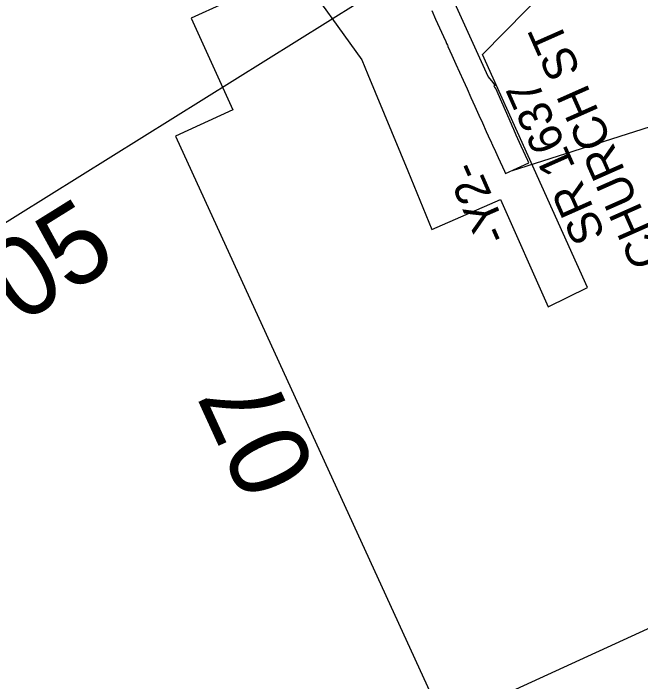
# Model space of a CAD drawing. Extents: x 2038094 to 2053858, y 751760 to 764312.
# Drawn here: x 2047889 to 2048875, y 757655 to 758704 of the extents above; entities that cross this region are included whole.
import ezdxf

# ---------------------------------------------------------------- set-up
doc = ezdxf.new("R2010")
doc.units = 0
for name, color, linetype in [('Old_Level_14', 7, 'Continuous'), ('Old_Level_2', 7, 'Continuous'), ('Prop Shade Light', 7, 'Continuous'), ('Scratch_Level_1', 7, 'Continuous'), ('Sheet Data Field CELL', 7, 'Continuous')]:
    doc.layers.add(name, color=color, linetype=linetype)

msp = doc.modelspace()

# ---------------------------------------------------------------- linework, layer by layer
at = {"layer": 'Old_Level_14'}
msp.add_lwpolyline([(2048673.4, 758457.4), (2049311, 758660.4), (2050071.9, 759134.4)], dxfattribs=at)
at = {"layer": 'Old_Level_2'}
msp.add_lwpolyline([(2048317.2, 760000), (2048471.5, 759555.8), (2048507.6, 759437.8), (2048294.2, 759356.6), (2048238, 759335.1), (2048278.4, 759249.5), (2048363.9, 759055.2), (2048389.2, 758999.6), (2048295.5, 758998.9), (2048328.8, 758810.8), (2048335.6, 758772), (2048436.9, 758631), (2048446.2, 758607.9), (2048508.9, 758456.6), (2048547, 758364.6), (2048654.6, 758411.5), (2048729.6, 758243.2), (2048791.5, 758273.4), (2048626.2, 758639.2), (2049007.2, 759026.2)], dxfattribs=at)
at = {"layer": 'Prop Shade Light'}
for p, q in [((2048672, 758529.8), (2048647.3, 758585.8)), ((2048662.4, 758452.5), (2048699, 758469.3))]:
    msp.add_line(p, q, dxfattribs=at)
for points in [[(2048635.1, 758605.1), (2048569.7, 758749.3), (2048552.9, 758786.5), (2048330.9, 759276.3)], [(2048546.6, 758708.5), (2048552.8, 758694.9), (2048559, 758681.2), (2048565.1, 758667.6), (2048568.6, 758659.7), (2048569.4, 758658.1), (2048570, 758656.7), (2048571.3, 758653.9), (2048571.7, 758653), (2048572.1, 758652.1), (2048578.3, 758638.3), (2048584.5, 758624.5), (2048590.4, 758611.5)], [(2048590.4, 758611.5), (2048596, 758599.2), (2048602.2, 758585.5), (2048608.3, 758571.8), (2048614.5, 758558.2), (2048620.7, 758544.4), (2048626.2, 758532.3), (2048632.4, 758518.7), (2048638.6, 758505), (2048640.4, 758501), (2048640.8, 758500.2), (2048641.1, 758499.6), (2048642.2, 758497.1), (2048642.9, 758495.6), (2048644.5, 758492), (2048651, 758477.7), (2048660.8, 758456), (2048662.4, 758452.5)], [(2048647.3, 758585.8), (2048645.9, 758588), (2048645.5, 758588.8), (2048644.8, 758590.1), (2048646.5, 758591.1), (2048640.9, 758598.3), (2048635.1, 758605.1)], [(2048699, 758469.3), (2048697.4, 758472.9), (2048687.2, 758495.5), (2048679.4, 758512.9), (2048675.4, 758521.9), (2048673.1, 758527.3), (2048672, 758529.8)]]:
    msp.add_lwpolyline(points, dxfattribs=at)
at = {"layer": 'Scratch_Level_1'}
for points in [[(2047231.5, 758989.4), (2047651.9, 758235.9), (2048432.2, 758721.8), (2048320.7, 758901.4), (2048734.5, 759088.9), (2048387.9, 759645.5), (2047820.9, 759388.6)], [(2048565.5, 757590.6), (2049520.1, 758027.9), (2048982.6, 759201.3), (2048218.8, 758855.3), (2048270.2, 758743.1), (2048168.3, 758696.4), (2048234.1, 758552.7), (2048143.7, 758511.3)]]:
    msp.add_lwpolyline(points, close=True, dxfattribs=at)

# ---------------------------------------------------------------- texts
for s, rotation, p in [('05', 31.918, (2047898.9, 758214.6)), ('07', 114.6116, (2048367.6, 757984.6))]:
    msp.add_text(s, height=125, rotation=rotation, dxfattribs=at).set_placement(p)
at = {"layer": 'Sheet Data Field CELL'}
for s, p in [('CHURCH ST', (2048912.6, 758317.8)), ('SR 1637', (2048820.4, 758355.9)), ('-Y2-', (2048670.3, 758354.8))]:
    msp.add_text(s, height=52.5, rotation=113.9161, dxfattribs=at).set_placement(p)

doc.saveas('drawing.dxf')
